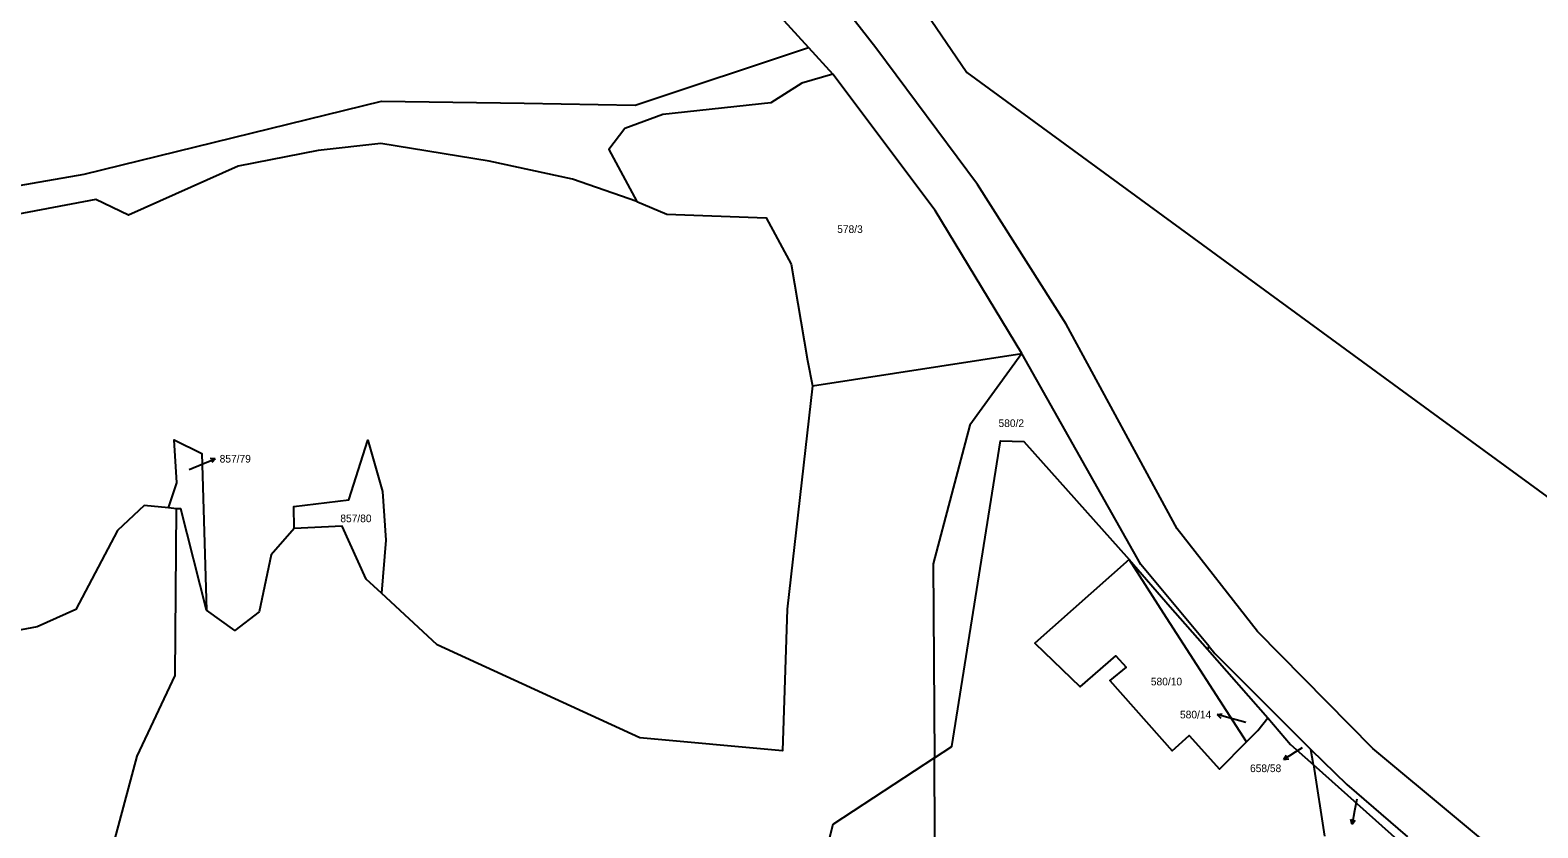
# Model space of a CAD drawing. Extents: x -887272 to -880188, y -1026687 to -1021896.
# Drawn here: x -884435.6 to -884099.9, y -1023848.1 to -1023670.6 of the extents above; entities that cross this region are included whole.
import ezdxf

# ---------------------------------------------------------------- set-up
doc = ezdxf.new("R2010")
doc.units = 0
for name, color, linetype in [('Hranice parcel', 7, 'Continuous'), ('Parcelní čísla', 7, 'Continuous'), ('Pop  PČ popisy', 7, 'Continuous')]:
    doc.layers.add(name, color=color, linetype=linetype)

msp = doc.modelspace()

# ---------------------------------------------------------------- linework, layer by layer
at = {"layer": 'Hranice parcel'}
for p, q in [((-884262.23, -1023674.41), (-884256.84, -1023680.32)), ((-884261.34, -1023749.76), (-884214.78, -1023742.56)), ((-884403, -1023777.1), (-884404.79, -1023776.92)), ((-884173.38, -1023808.38), (-884173, -1023807.74)), ((-884173.38, -1023808.38), (-884159.96, -1023823.61)), ((-884173, -1023807.74), (-884171.77, -1023809.33)), ((-884171.77, -1023809.33), (-884150.38, -1023830.66)), ((-884149.84, -1023834.12), (-884150.38, -1023830.66)), ((-884130.36, -1023851.44), (-884149.84, -1023834.12)), ((-884149.84, -1023834.12), (-884147.35, -1023849.97))]:
    msp.add_line(p, q, dxfattribs=at)
for points in [[(-884407.12, -1023523.4), (-884369.04, -1023563.52), (-884342.76, -1023586.12), (-884308.6, -1023622.08), (-884274.86, -1023660.54), (-884262.23, -1023674.41)], [(-884243.99, -1023654.98), (-884227, -1023680), (-884122.02, -1023756.68), (-884019.28, -1023831.73)], [(-883756.5, -1024023.04), (-883767.66, -1024020.24), (-883797.06, -1024014.34), (-883842.62, -1024005.56), (-883874.8, -1024002.84), (-883906.02, -1023994.68), (-883929.04, -1023982.78), (-884005.12, -1023932.5), (-884033.98, -1023912.56), (-884080.28, -1023877.34), (-884136.58, -1023830.48), (-884162.3, -1023804.42), (-884180.14, -1023781.6), (-884204.86, -1023736.02), (-884224.62, -1023704.92), (-884247.24, -1023674.52), (-884253.66, -1023666.34), (-884254.22, -1023665.64)], [(-884568.81, -1023718.25), (-884554.44, -1023716.55), (-884516.44, -1023711.22), (-884503.64, -1023712.63), (-884484.54, -1023713.24), (-884423.52, -1023702.61), (-884357.31, -1023686.33), (-884325.59, -1023686.84), (-884300.88, -1023687.28), (-884262.23, -1023674.41)], [(-884256.84, -1023680.32), (-884263.76, -1023682.36), (-884270.64, -1023686.74), (-884294.66, -1023689.34), (-884303.14, -1023692.48), (-884306.74, -1023697.12), (-884300.5, -1023708.68)], [(-884214.78, -1023742.56), (-884234.08, -1023710.72), (-884256.84, -1023680.32)], [(-884300.5, -1023708.68), (-884314.81, -1023703.7), (-884333.37, -1023699.73), (-884357.49, -1023695.78), (-884371.45, -1023697.32), (-884389.25, -1023700.82), (-884413.68, -1023711.71), (-884420.93, -1023708.22), (-884470.9, -1023717.71), (-884512.9, -1023719.25), (-884542.91, -1023724.55), (-884569.02, -1023734.25), (-884589.87, -1023741.38)], [(-884300.5, -1023708.68), (-884293.78, -1023711.52), (-884271.68, -1023712.36), (-884266.08, -1023722.64), (-884262.44, -1023744.08), (-884261.34, -1023749.76)], [(-884214.78, -1023742.56), (-884226.34, -1023758.5), (-884234.46, -1023789.36), (-884234.22, -1023832.56)], [(-884173, -1023807.74), (-884188.26, -1023789.5), (-884214.78, -1023742.56)], [(-884261.34, -1023749.76), (-884266.98, -1023799.44), (-884268.04, -1023830.96), (-884299.8, -1023828.08), (-884344.94, -1023807.36), (-884357.36, -1023795.92)], [(-884404.79, -1023776.92), (-884402.93, -1023771.32), (-884403.48, -1023761.74), (-884397.31, -1023764.76), (-884396.28, -1023799.68)], [(-884376.76, -1023781.46), (-884376.88, -1023776.58), (-884364.58, -1023775.12), (-884360.38, -1023761.82), (-884357.14, -1023773.22), (-884356.37, -1023784.12), (-884357.36, -1023795.92)], [(-884234.22, -1023832.56), (-884230.32, -1023830.01), (-884219.53, -1023761.97), (-884214.28, -1023762.15), (-884190.86, -1023788.4)], [(-884404.79, -1023776.92), (-884410.2, -1023776.36), (-884416.12, -1023781.9), (-884425.4, -1023799.52), (-884433.98, -1023803.38), (-884459.8, -1023808.18), (-884498.12, -1023798.54), (-884539.98, -1023794.36), (-884578.92, -1023786.72), (-884618.32, -1023789.66), (-884637.32, -1023785.54)], [(-884429.56, -1023876.82), (-884417.56, -1023853.78), (-884411.72, -1023832.2), (-884403.24, -1023814.2), (-884403, -1023777.1)], [(-884396.28, -1023799.68), (-884402.04, -1023777.14), (-884403, -1023777.1)], [(-884376.76, -1023781.46), (-884381.88, -1023787.32), (-884384.54, -1023800.02), (-884389.96, -1023804.16), (-884396.28, -1023799.68)], [(-884357.36, -1023795.92), (-884360.74, -1023792.8), (-884366.08, -1023780.98), (-884376.76, -1023781.46)], [(-884190.86, -1023788.4), (-884211.88, -1023807.01), (-884201.74, -1023816.74), (-884193.79, -1023809.84), (-884191.51, -1023812.33), (-884195.16, -1023815.31), (-884181.26, -1023830.99), (-884177.52, -1023827.58), (-884170.7, -1023835.03), (-884164.73, -1023829)], [(-884190.86, -1023788.4), (-884181.7, -1023798.95), (-884173.38, -1023808.38)], [(-884164.73, -1023829), (-884183.2, -1023800.3), (-884190.86, -1023788.4)], [(-884164.73, -1023829), (-884162.18, -1023826.42), (-884159.96, -1023823.61)], [(-884159.96, -1023823.61), (-884154.92, -1023829.6), (-884149.84, -1023834.12)], [(-884150.38, -1023830.66), (-884142.38, -1023838.5), (-884128.87, -1023850.09)], [(-884234.22, -1023832.56), (-884256.83, -1023847.38), (-884264.84, -1023879.03)], [(-884235.04, -1023890.58), (-884235.45, -1023870.15), (-884234.12, -1023849.8), (-884234.22, -1023832.56)]]:
    msp.add_lwpolyline(points, dxfattribs=at)
at = {"layer": 'Pop  PČ popisy'}
for p, q in [((-884400.17, -1023768.35), (-884397.14, -1023767.1)), ((-884397.14, -1023767.1), (-884394.36, -1023765.98)), ((-884394.36, -1023765.98), (-884395.47, -1023765.89)), ((-884394.36, -1023765.98), (-884395.1, -1023766.82)), ((-884171.25, -1023822.93), (-884170.15, -1023822.71)), ((-884168.35, -1023823.71), (-884171.25, -1023822.93)), ((-884171.25, -1023822.93), (-884170.41, -1023823.68)), ((-884164.88, -1023824.67), (-884168.35, -1023823.71)), ((-884153.86, -1023831.29), (-884156.41, -1023832.88)), ((-884156.41, -1023832.88), (-884155.82, -1023831.93)), ((-884152.31, -1023830.32), (-884153.86, -1023831.29)), ((-884156.41, -1023832.88), (-884155.29, -1023832.77)), ((-884140.18, -1023841.72), (-884140.65, -1023844.32)), ((-884140.65, -1023844.32), (-884141.17, -1023847.28)), ((-884141.17, -1023847.28), (-884141.49, -1023846.2)), ((-884141.17, -1023847.28), (-884140.5, -1023846.38))]:
    msp.add_line(p, q, dxfattribs=at)

# ---------------------------------------------------------------- texts
at = {"layer": 'Parcelní čísla'}
for s, p in [('578/3', (-884255.86, -1023715.7)), ('580/2', (-884219.94, -1023758.9)), ('857/79', (-884393.37, -1023766.81)), ('857/80', (-884366.5, -1023780.09)), ('580/10', (-884186.02, -1023816.41)), ('580/14', (-884179.53, -1023823.76)), ('658/58', (-884163.94, -1023835.72))]:
    msp.add_text(s, height=1.7, dxfattribs=at).set_placement(p)

doc.saveas('drawing.dxf')
